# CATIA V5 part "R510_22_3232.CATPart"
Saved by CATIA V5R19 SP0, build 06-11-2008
Material "Steel": density 7860 kg/m3, Young's modulus 2e+11 Pa, Poisson ratio 0.266, thermal expansion 1.17e-05 1/K
Bounding box of the stored display mesh (mm): x -16 to 15.969, y -15.868 to 15.873, z 0 to 100
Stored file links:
  G:\Podręcznik\CD\Narzędzia\Arkusz Excel\Modele narzędzi\R510.22-3232.CATPart
  C:\Program Files\Dassault Systemes\B19\intel_a\startup\materials\Catalog.CATMaterial
  F:\OSTATNIE\DesignTable2.xls
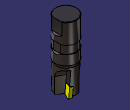
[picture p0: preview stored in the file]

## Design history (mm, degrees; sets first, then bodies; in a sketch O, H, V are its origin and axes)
Parameters
  CuttingType = "CUTTER"
  d = 32 mm {design table}
  D = 32 mm {design table}
  L = 100 mm {design table}
  l = 60 mm {design table}
  alfa = 11 deg {design table}
  gammap = 4 deg {design table}
  S = 4.76 mm {design table}
  epsilon = 85 deg {design table}
  lp = 16 mm {design table}
  x = 0.591 mm {design table}
  gammaf = -10 deg {design table}
  z = 3 {design table}
  teta = 120 deg {design table}
  `lp'` = 15.961 mm {design table}
  `lp''` = 9.4182 mm {design table}
Body1 "BODY" (main body), material "Steel"
  Sketch1 "sketch" on yz-plane, origin (0, 0, 0), H (0, 1, 0), V (0, 0, 1)
    line L1 (0, 2.5555) -> (15, 0.7137)
    line L2 (15, 0.7137) -> (15, 40)
    point P3 (15, 40)
    line L3 (15, 40) -> (15, 40)
    point P4 (16, 40)
    line L4 (16, 43.4583) -> (16, 58)
    point P5 (16, 58)
    line L5 (16, 58) -> (15, 58)
    line L6 (15, 58) -> (15, 70)
    line L7 (15, 70) -> (16, 70)
    point P8 (16, 70)
    line L8 (16, 70) -> (16, 99.2929)
    line L9 (16, 99.2929) -> (15.2929, 100)
    line L10 (15.2929, 100) -> (0, 100)
    point P11 (0, 100)
    line L11 (0, 100) -> (0, 2.5555)
    construction line L12 (0, -29.1199) -> (0, 199.3445)
    point P12 (0, -29.1199)
    construction line L13 (0, 0.591) -> (16, 0.591)
    point P14 (0, 0.591)
    point P15 (16, 0.591)
    construction line L14 (0, 2.5555) -> (16, 0.591)
    axis line L15 (16, 0.591) -> (16, -5.0846)
    line L16 (15, 40) -> (16, 43.4583)
    point P17 (15, 40)
    length L6 = 12 {= 0.2*l}
    distance P3 H = 40 {= L-l}
    length L9 = 1
    angle L8 L9 = 45
    distance L6 L8 = 1
    distance L8 L11 = 16 {= d/2}
    length L13 = 16 {= D/2}
    distance H L13 = 0.591 {= x}
    distance L10 L7 = 30 {= 0.5*l}
    distance P15 L2 = 1
    distance P4 P5 = 18 {= 0.3*l}
    length L16 = 3.6 {= 0.2*(0.3*l)}
    angle L1 L2 = 83
    vertical: L2 V, L4 V, L6 V, L8 V, L11 V, L12 V, L15 V
    horizontal: L3 H, L5 H, L7 H, L10 H, L13 H
    coincidence: P8 L4, P11 V, P12 V, L1 L14, P14 L12, L3 P4, L4 P4, P3 P17
  Shaft1: profile Sketch1, axis Z axis, angle 360
  Fillet1: radius 1.6 {= 0.1*D/2}, on edge [face of Shaft1 from Sketch1.L1 | face of Shaft1 from Sketch1.L2]
  Sketch2 on zx-plane, origin (0, 0, 0), H (-1, 0, 0), V (0, 0, 1)
    line L1 (-14, 100) -> (-14, 82)
    line L2 (-14, 82) -> (-16, 80)
    line L3 (-16, 80) -> (-16, 72)
    line L4 (-16, 72) -> (-14, 70)
    point P5 (-14, 70)
    line L5 (-14, 70) -> (-14, 58)
    line L6 (-14, 58) -> (-16, 56)
    point P7 (-16, 56)
    line L7 (-16, 56) -> (-16, 56)
    line L8 (-16, 56) -> (-19, 56)
    line L9 (-19, 56) -> (-19, 100)
    line L10 (-19, 100) -> (-14, 100)
    reference projected line E1 through (0, 0) direction (0, 1) from axis of face of Shaft1 from Sketch1.L8
    reference projected line E2 (-9.2929, 100) -> (9.2929, 100) from edge [face of Shaft1 from Sketch1.L9 | face of Shaft1 from Sketch1.L10]
    distance L3 E1 = 16 {= d/2}
    distance L1 L3 = 2
    angle L2 L3 = 45
    angle L4 L3 = 45
    length L5 = 12 {= l*0.2}
    length L1 = 18 {= 0.3*l}
    distance P5 L10 = 30 {= 0.5*l}
    distance L9 L1 = 5
    distance L7 L5 = 2
    angle L5 L6 = 45
    vertical: L1 V, L3 V, L5 V, L7 V, L9 V
    horizontal: L8 H, L10 H
    coincidence: L10 E2, L1 L5, P7 L8
  Pocket1: profile Sketch2, direction (0, -1, 0), length 8, mirrored extent
  Plane1: type Angle, Angle 150, Direction Z axis, RefPlane yz-plane
  Plane2: type Offset, Offset 1, RefPlane Plane1, reversed
  Sketch3 "gammap_os_obrotu" on Plane2, origin (0.866, -0.5, 0), H (-0.5, -0.866, 0), V (0, 0, 1)
    line L1 (1.3076, 0) -> (-0.9434, 0)
    reference intersected line E1 through (0, 0) direction (-1, 0) from xy-plane
    horizontal: L1 H
    coincidence: E1 L1
  Plane3 "gammap": type Angle, Angle -4 {= -gammap}, Direction Sketch3, RefPlane Plane2
  Plane4: type Offset, Offset 0.5, RefPlane Plane3, reversed
  Sketch4 on Plane4, origin (1.2859, -0.7424, 0.2345), H (-0.5, -0.866, 0), V (-0.0604, 0.0349, 0.9976)
    line L1 (-16, -2.3223) -> (-16, 6.2448)
    distance V L1 = 16 {= D/2}
  Plane5 "gammaf": type Angle, Angle 10 {= -gammaf}, Direction Sketch4, RefPlane Plane4
  Plane6: type Offset, Offset 0.5, RefPlane Plane5
  Plane7: type Angle, Angle 90, Direction Sketch4, RefPlane Plane5
  Sketch5 on Plane7, origin (4.8074, 14.7365, -0.5172), H (0.9396, -0.3424, 0.0007), V (0.0035, 0.0116, 0.9999)
    point P1 (4.7799, 0.5137)
    line L1 (4.7799, 0.5137) -> (-0.032, 1.1133)
    line L2 (-0.032, 1.1133) -> (-0.9938, 15.2301)
    line L3 (-0.9938, 15.2301) -> (3.6923, 16.4767)
    line L4 (3.6923, 16.4767) -> (4.7799, 0.5137)
    reference projected line E1 (4.9209, -1.5569) -> (4.3386, 6.9904) from Sketch4
    construction line L5 (3.6923, 16.4767) -> (-1.2573, 16.1395)
    axis line L6 (4.7799, 0.5137) -> (1.0543, 0.2599)
    reference intersected line E2 through (-0.0001, 0.5172) direction (-1, 0.0007) from xy-plane
    distance L2 L4 = 4.76 {= S}
    length L4 = 16 {= lp}
    angle L5 L3 = 11 {= alfa}
    angle L6 L1 = 11 {= alfa}
    coincidence: L4 E1, P1 E2
    perpendicularity: L5 L2
    parallelism: L6 L5
  Plane8: type Offset, Offset 16 {= D/2}, RefPlane Plane1, reversed
  Sketch6 on Plane8, origin (13.8564, -8, 0), H (-0.5, -0.866, 0), V (0, 0, 1)
    line L1 (-5.6396, -3) -> (-5.6396, 25.1125)
    arc A1 centre (-17.6396, 25.1125) radius 12 from (-5.6396, 25.1125) to (-16, 37) ccw
    point P4 (-16, 37)
    line L2 (-16, 37) -> (-16, -3)
    point P5 (-16, -3)
    line L3 (-16, -3) -> (-5.6396, -3)
    axis line L4 (-16, -3) -> (-5.6396, -2.0936)
    point P6 (-16, -3)
    point P7 (-5.6396, -2.0936)
    reference projected line E1 (-9, 40) -> (9, 40) from edge [face of Shaft1 from Sketch1.L2 | face of Shaft1 from Sketch1.L16]
    distance L2 V = 16 {= D/2}
    angle L4 L2 = 85 {= epsilon}
    distance E1 P4 = 3
    radius A1 = 12
    distance H L3 = 3
    length L4 = 10.4 {= 0.65*lp}
    vertical: L1 V, L2 V
    horizontal: L3 H
    tangency: L1 A1
    coincidence: P6 P5, P7 L1
  Pocket2: profile Sketch6, direction (-0.866, 0.5, 0), up to Plane6
  CircPattern1: of Pocket2, instances 3 {= z}, angular step 120 {= teta}, axis from Z axis
  Sketch7 on Plane5, origin (4.0216, -1.2749, 0.6986), H (-0.3414, -0.9399, -0.0041), V (-0.066, 0.0196, 0.9976)
    line L1 (-15.5758, 15.2346) -> (-6.0272, 16.2266)
    point P1 (-15.5758, 15.2346)
    reference projected point E1 (-15.5758, 15.2346) from vertex [element of Sketch5 | element of Sketch5]
    reference projected line E2 (-15.3109, -1.0639) -> (-15.4734, 8.9348) from Sketch5.L4
    length L1 = 9.6 {= 0.6*lp}
    angle E2 L1 = 85 {= epsilon}
    coincidence: P1 E1
  Slot1: profile Sketch5, centre curve Sketch7
  CircPattern2: of Slot1, instances 3 {= z}, angular step 120 {= teta}, axis from Z axis
Body2 "INSERTS"
  Sketch8 "CUT" on yz-plane, origin (0, 0, 0), H (0, 1, 0), V (0, 0, 1)
    line L1 (6.6177, 0.8208) -> (16, 0)
    point P2 (16, 0)
    line L2 (16, 0) -> (16, 15.961)
    line L3 (16, 15.961) -> (6.6177, 16.7819)
    line L4 (6.6177, 16.7819) -> (6.6177, 0.8208)
    angle L3 L4 = 85
    length L2 = 15.961 {= `lp'`}
    length L1 = 9.4182 {= `lp''`}
    distance L2 V = 16 {= D/2}
    vertical: L2 V, L4 V
    parallelism: L3 L1
    coincidence: P2 H
  Sketch9 "NOCUT" on yz-plane, origin (0, 0, 0), H (0, 1, 0), V (0, 0, 1)
    axis line L1 (16, 0) -> (0, 1.3998)
    point P1 (0, 1.3998)
    point P2 (16, 0)
    reference projected line E1 (4.0684, 1.0439) -> (10.0456, 0.5209) from Sketch8.L1
    reference projected point E2 (16, 0) from vertex [element of Sketch8 | element of Sketch8]
    line L2 (0, 1.3998) -> (6.6177, 0.8208)
    point P3 (6.6177, 0.8208)
    line L3 (6.6177, 0.8208) -> (6.6177, 16.7819)
    line L4 (6.6177, 16.7819) -> (15, 16.0485)
    line L5 (15, 16.0485) -> (15, 40)
    line L6 (15, 40) -> (16, 40)
    line L7 (16, 40) -> (16, 58)
    line L8 (16, 58) -> (15, 58)
    line L9 (15, 58) -> (15, 70)
    line L10 (15, 70) -> (16, 70)
    point P11 (16, 70)
    line L11 (16, 70) -> (16, 99.2929)
    point P12 (16, 100)
    line L12 (15.2929, 100) -> (0, 100)
    point P13 (0, 100)
    line L13 (0, 100) -> (0, 1.3998)
    line L14 (16, 99.2929) -> (15.2929, 100)
    length L9 = 12 {= 0.2*l}
    length L7 = 18 {= 0.3*l}
    distance L6 H = 40 {= L-l}
    distance L11 L13 = 16 {= d/2}
    distance L9 L11 = 1
    distance P3 P2 = 9.4182 {= `lp''`}
    distance L9 L7 = 1
    distance L5 P2 = 1
    length L3 = 15.961 {= `lp'`}
    angle L10 L9 = 90
    distance P11 P12 = 30 {= 0.5*l}
    angle L11 L14 = 45
    length L14 = 1
    coincidence: P1 V, L1 E1, P2 E2, P13 V, L11 P12, L12 P12
    parallelism: L2 L1, L4 L1
    vertical: L3 V, L5 V, L7 V, L9 V, L11 V, L13 V
    horizontal: L6 H, L8 H, L12 H
  Sketch10 on Plane7, origin (4.8074, 14.7365, -0.5172), H (0.9396, -0.3424, 0.0007), V (0.0035, 0.0116, 0.9999)
    point P1 (4.7799, 0.5137)
    line L1 (4.7799, 0.5137) -> (-0.032, 1.1133)
    line L2 (-0.032, 1.1133) -> (-0.9938, 15.2301)
    line L3 (-0.9938, 15.2301) -> (3.6923, 16.4767)
    line L4 (3.6923, 16.4767) -> (4.7799, 0.5137)
    reference intersected line E1 through (4.7631, 0.76) direction (0.068, -0.9977) from Plane5
    reference intersected line E2 through (-0.0001, 0.5172) direction (-1, 0.0007) from xy-plane
    construction line L5 (3.6923, 16.4767) -> (-7.2625, 15.7304)
    axis line L6 (4.7799, 0.5137) -> (-1.8943, 0.059)
    distance L2 L4 = 4.76 {= S}
    length L4 = 16 {= lp}
    angle L3 L5 = 11 {= alfa}
    angle L6 L1 = 11 {= alfa}
    coincidence: L4 E1, E2 P1
    perpendicularity: L5 L2
    parallelism: L6 L5
  Sketch11 on Plane5, origin (4.0216, -1.2749, 0.6986), H (-0.3414, -0.9399, -0.0041), V (-0.066, 0.0196, 0.9976)
    line L1 (-15.5758, 15.2346) -> (-6.0272, 16.2266)
    point P1 (-15.5758, 15.2346)
    reference projected point E1 (-15.5758, 15.2346) from vertex [element of Sketch10 | element of Sketch10]
    reference projected line E2 (-15.3159, -0.752) -> (-15.4785, 9.2467) from Sketch10.L4
    angle L1 E2 = 85 {= epsilon}
    length L1 = 9.6 {= 0.6*lp}
    coincidence: P1 E1
  Rib1: profile Sketch10, centre curve Sketch11
  CircPattern3: of the body so far, instances 3 {= z}, angular step 120 {= teta}, axis from Z axis
  Sketch12 on face of Rib1, origin (0.1546, 0.2005, 2.0242), H (0.7983, -0.5955, -0.09), V (-0.5837, -0.8018, 0.1281)
    point P1 (-0.2029, -15.945)
    line L1 (-0.2029, -15.945) -> (-4.5937, -13.6468)
    line L2 (-4.5937, -13.6468) -> (-4.8493, -14.5574)
    point P3 (-4.8493, -14.5574)
    line L3 (-4.8493, -14.5574) -> (-0.2029, -15.945)
    reference projected point E1 (-0.2029, -15.945) from vertex [face of Rib1 | face of Rib1 | face of Rib1]
    reference projected line E2 (-4.46, -14.6737) -> (-1.356, -15.6006) from edge [face of Rib1 | face of Rib1]
    reference projected point E3 (-4.8493, -14.5574) from vertex [face of Rib1 | face of Rib1 | face of Rib1]
    reference projected line E4 (-3.2503, -8.8593) -> (-1.6293, -3.0824) from edge [face of Rib1 | face of Rib1]
    angle L1 L3 = 11
    coincidence: E1 P1, L3 E2, P3 E3, L2 E4
  Pocket3: profile Sketch12, direction along edge [face of Rib1 | face of Rib1], length 16 {= lp}
  CircPattern4: of Pocket3, instances 3 {= z}, angular step 120 {= teta}, axis from Z axis
Relations
  design table, configuration 6, drives d, D, L, l, alfa, gammap, S, epsilon, lp, x, gammaf, z, teta, `lp'`, `lp''`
